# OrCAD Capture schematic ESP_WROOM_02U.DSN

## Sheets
1 00 Block Diagram: title: ESP-WROOM-02U
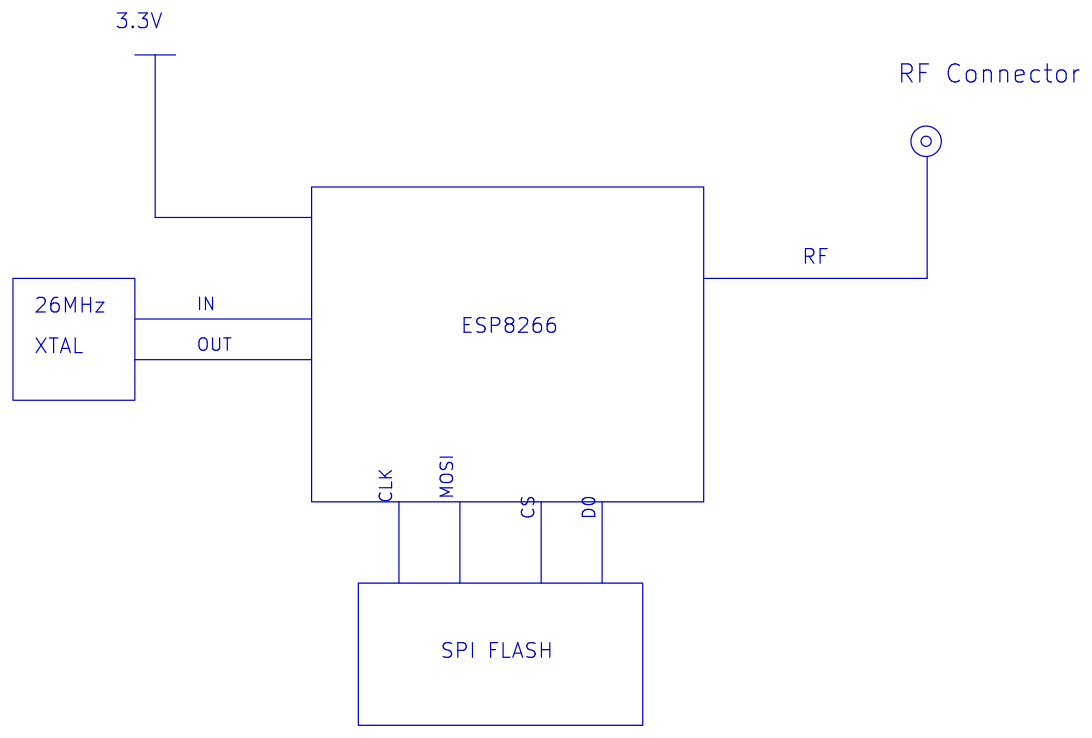
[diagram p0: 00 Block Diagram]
2 01 ESP_WROOM02_UFL: size A3
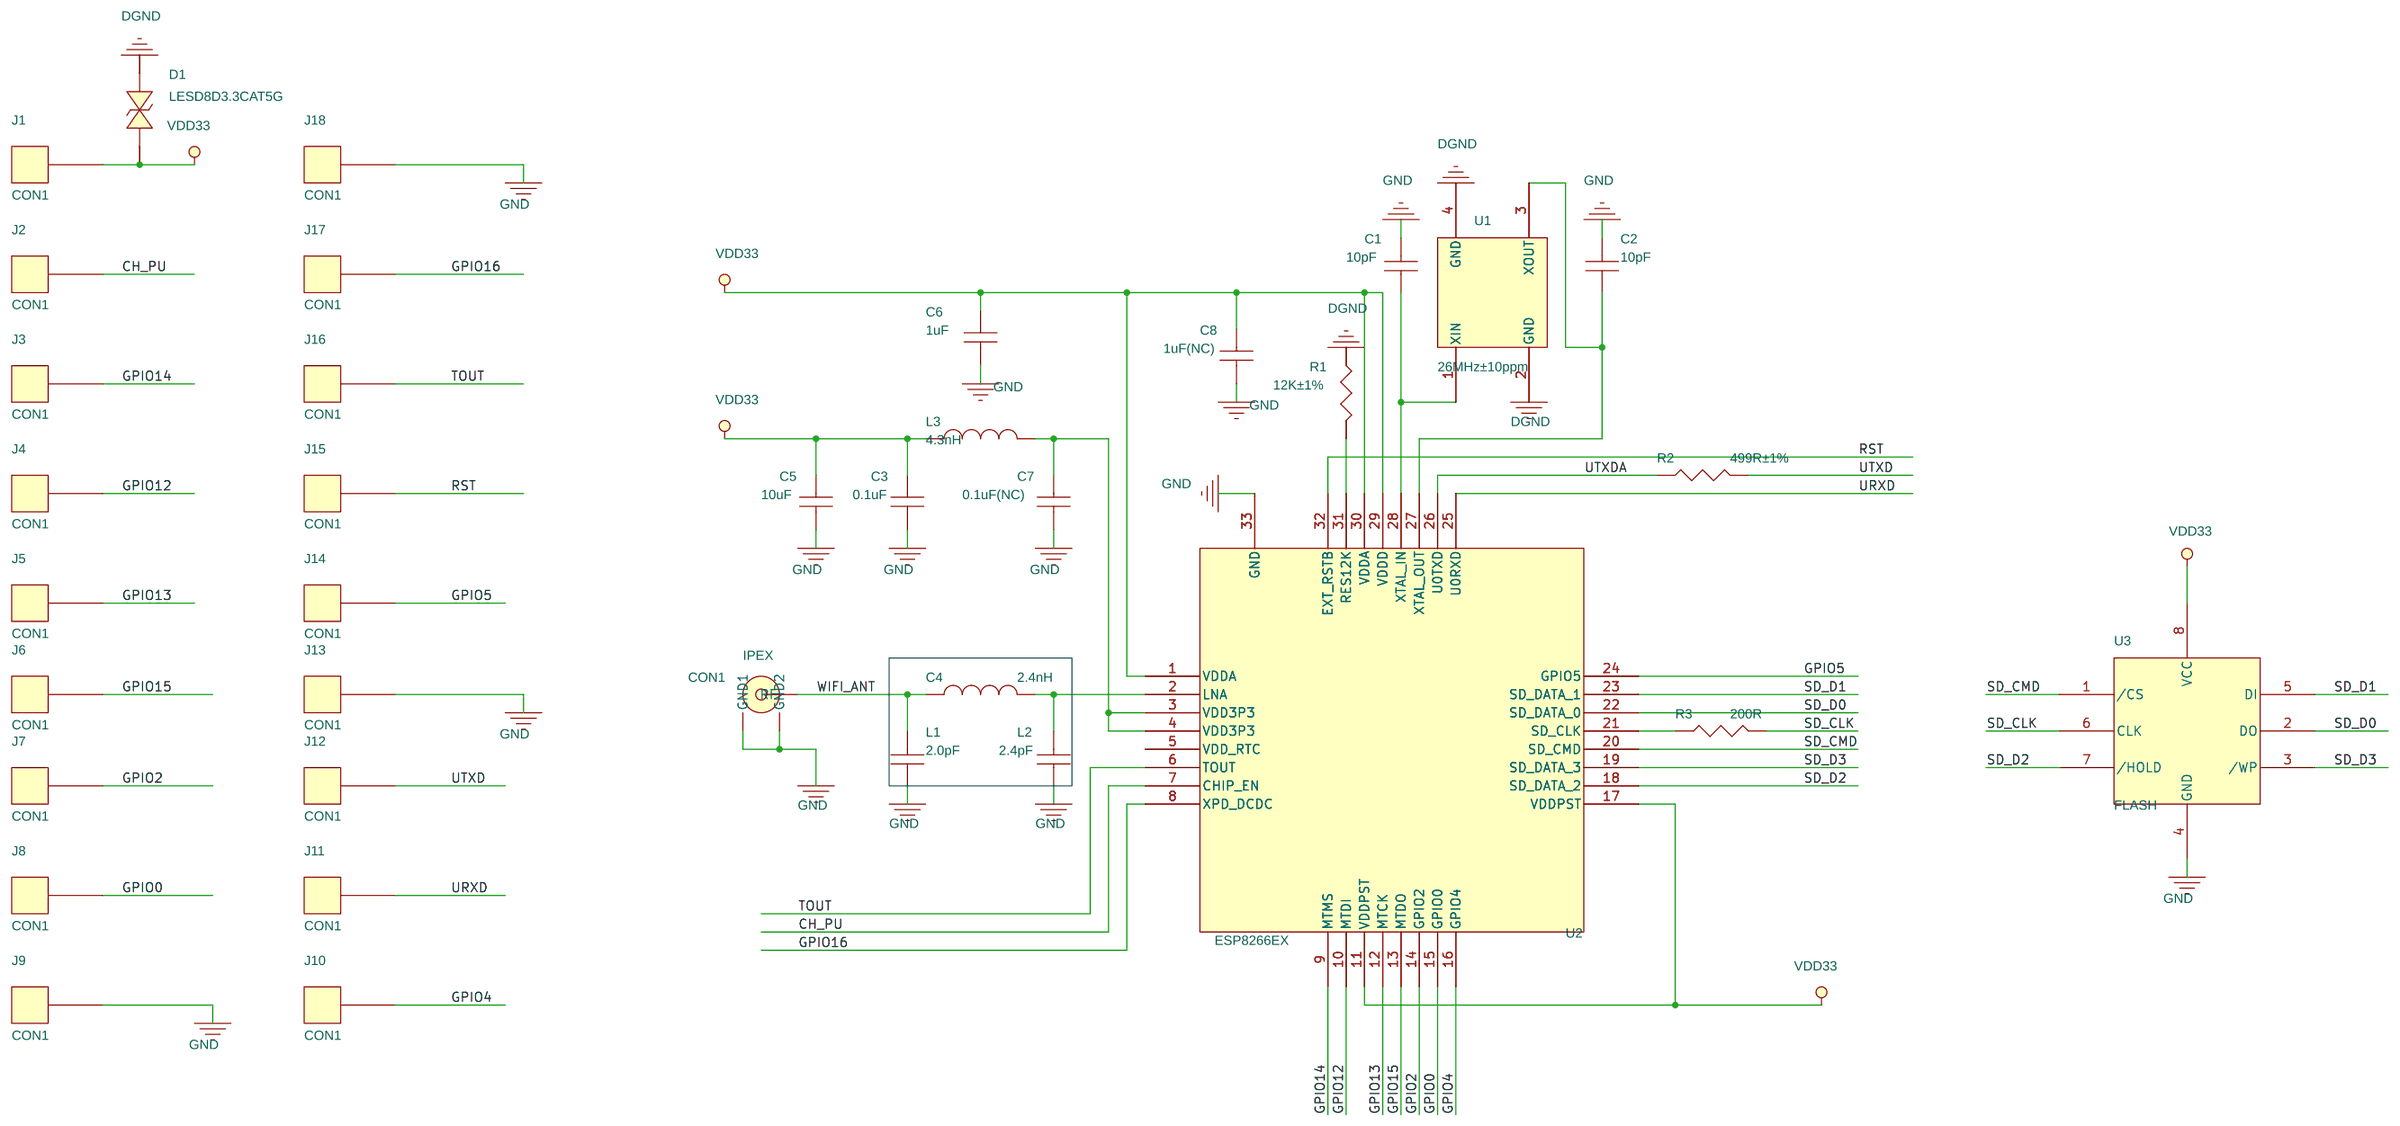
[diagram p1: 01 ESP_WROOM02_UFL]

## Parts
C1  10pF  [0402A]
C2  10pF  [0402A]
C3  0.1uF  [0402A]
C4  2.4nH  [L0402//A]
C5  10uF  [0603C]
C6  1uF  [0603C]
C7  0.1uF(NC)  [0201C]
C8  1uF(NC)  [0603C]
CON1  IPEX  [ECT818000368]
D1  LESD8D3.3CAT5G  [SOD882]
J1  CON1  [SPAD]
J2  CON1  [SPAD]
J3  CON1  [SPAD]
J4  CON1  [SPAD]
J5  CON1  [SPAD]
J6  CON1  [SPAD]
J7  CON1  [SPAD]
J8  CON1  [SPAD]
J9  CON1  [SPAD]
J10  CON1  [SPAD]
J11  CON1  [SPAD]
J12  CON1  [SPAD]
J13  CON1  [SPAD]
J14  CON1  [SPAD]
J15  CON1  [SPAD]
J16  CON1  [SPAD]
J17  CON1  [SPAD]
J18  CON1  [SPAD]
L1  2.0pF  [0402A]
L2  2.4pF  [0402A]
L3  4.3nH  [0201C]
R1  12K±1%  [0201R]
R2  499R±1%  [0201R]
R3  200R  [0402A]
U1  26MHz±10ppm  [XTAL2520]
U2  ESP8266EX  [QFN32_3.7X3.7]
U3  FLASH  [SOIC08-W]

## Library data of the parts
C1-C3 C5-C8 L1 L2 = CAP_NP
C4 L3 = INDUCTOR
CON1 = IPEX_0
D1 = DIODE_BI-DIR_TRIG: Options: ESD
J1-J18 = CON1
R1-R3 = RESISTOR
U1 = X1_0
U2 = ESP8080_1
U3 = FLASH_1

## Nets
GND: C1.2 C2.2 C3.2 C5.2 C6.2 C7.2 C8.2 CON1.2(GND1) CON1.3(GND2) D1.2 J9.1 J13.1 J18.1 L1.1 L2.1 R1.1 U1.2(GND) U1.4(GND) U2.33(GND) U3.4(GND)
VDD33: C3.1 C5.1 C6.1 C8.1 D1.1 J1.1 L3.1 U2.1(VDDA) U2.11(VDDPST) U2.17(VDDPST) U2.29(VDDD) U2.30(VDDA) U3.8(VCC)
VDD_RTC: U2.5(VDD_RTC)
CH_PU: J2.1 U2.7(CHIP_EN)
GPIO0: J8.1 U2.15(GPIO0)
GPIO2: J7.1 U2.14(GPIO2)
GPIO4: J10.1 U2.16(GPIO4)
GPIO5: J14.1 U2.24(GPIO5)
GPIO12: J4.1 U2.10(MTDI)
GPIO13: J5.1 U2.12(MTCK)
GPIO14: J3.1 U2.9(MTMS)
GPIO15: J6.1 U2.13(MTDO)
GPIO16: J17.1 U2.8(XPD_DCDC)
RST: J15.1 U2.32(EXT_RSTB)
SD_CLK: R3.2 U3.6(CLK)
SD_CMD: U2.20(SD_CMD) U3.1(/CS)
SD_D0: U2.22(SD_DATA_0) U3.2(DO)
SD_D1: U2.23(SD_DATA_1) U3.5(DI)
SD_D2: U2.18(SD_DATA_2) U3.7(/HOLD)
SD_D3: U2.19(SD_DATA_3) U3.3(/WP)
TOUT: J16.1 U2.6(TOUT)
URXD: J11.1 U2.25(U0RXD)
UTXD: J12.1 R2.2
UTXDA: R2.1 U2.26(U0TXD)
WIFI_ANT: C4.1 CON1.1(RF) L1.2
N5630436: C7.1 L3.2 U2.3(VDD3P3) U2.4(VDD3P3)
N5630608: C2.1 U1.3(XOUT) U2.27(XTAL_OUT)
N5630726: C1.1 U1.1(XIN) U2.28(XTAL_IN)
N5630864: R1.2 U2.31(RES12K)
N5777066: R3.1 U2.21(SD_CLK)
N16684417: C4.2 L2.2 U2.2(LNA)

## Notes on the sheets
sheet 1
- 3.3V
- RF Connector
- RF
- 26MHz
- IN
- XTAL
- OUT
- ESP8266
- CLK
- MOSI
- CS
- D0
- SPI FLASH
